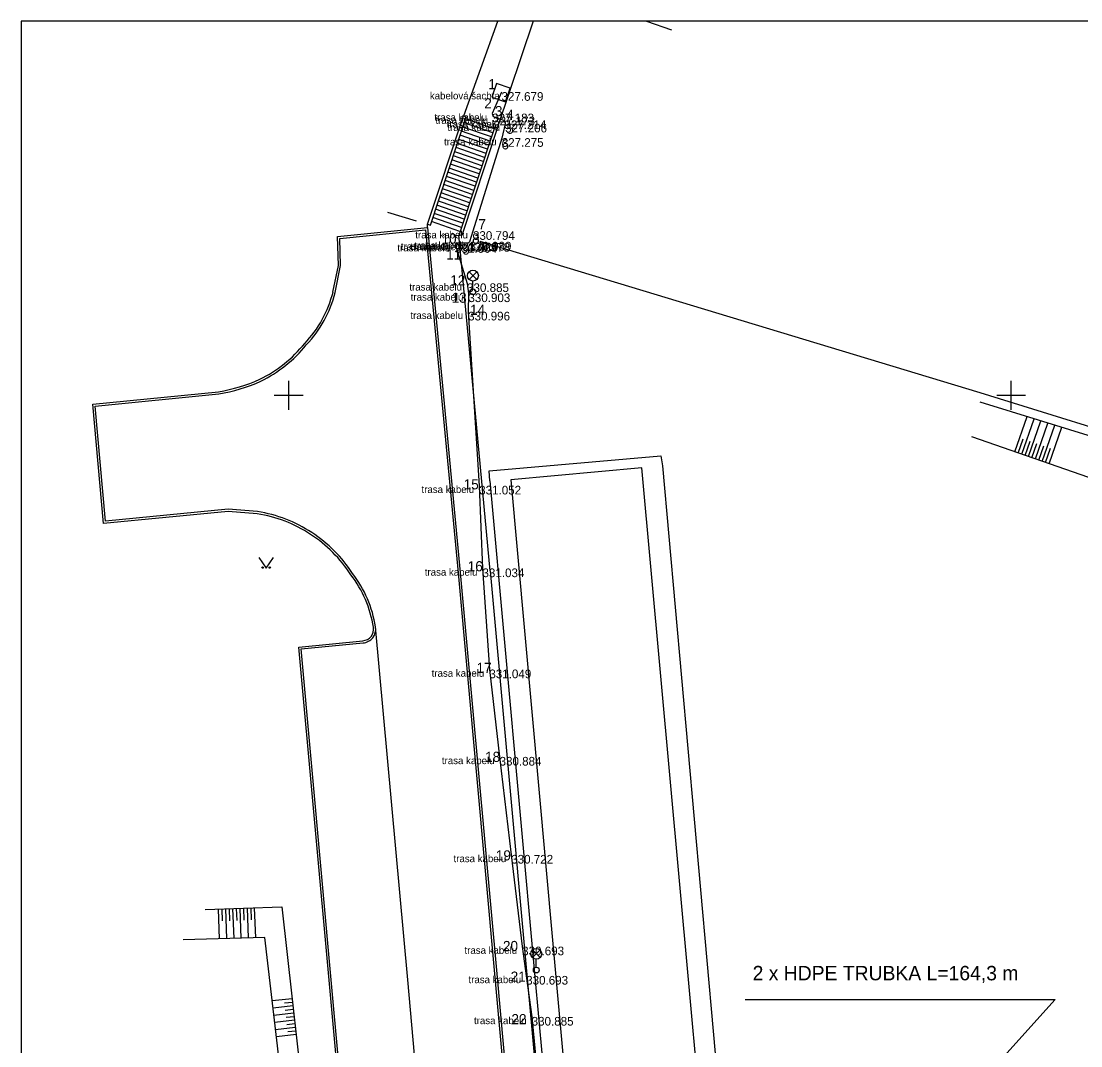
# Model space of a CAD drawing. Extents: x -825369 to -825236, y -1069674 to -1069474.
# Drawn here: x -825368.5 to -825295.2, y -1069545 to -1069474.1 of the extents above; entities that cross this region are included whole.
import ezdxf

# ---------------------------------------------------------------- set-up
doc = ezdxf.new("R2010")
doc.units = 0
for name, color, linetype in [('Vrstva 12', 7, 'Continuous'), ('Vrstva 18', 7, 'Continuous'), ('Vrstva 28', 7, 'Continuous'), ('Vrstva 29', 7, 'Continuous'), ('Vrstva 30', 7, 'Continuous'), ('Vrstva 31', 7, 'Continuous'), ('Vrstva 34', 7, 'Continuous'), ('Vrstva 37', 7, 'Continuous'), ('Vrstva 39', 7, 'Continuous'), ('Vrstva 4', 7, 'Continuous'), ('Vrstva 40', 7, 'Continuous'), ('Vrstva 41', 7, 'Continuous'), ('Vrstva 42', 7, 'Continuous'), ('Vrstva 49', 7, 'Continuous'), ('Vrstva 57', 7, 'Continuous'), ('Vrstva 58', 7, 'Continuous'), ('Vrstva 59', 7, 'Continuous'), ('Vrstva 60', 7, 'Continuous'), ('Vrstva 61', 7, 'Continuous'), ('Vrstva 63', 7, 'Continuous')]:
    doc.layers.add(name, color=color, linetype=linetype)

msp = doc.modelspace()

# ---------------------------------------------------------------- linework, layer by layer
at = {"layer": 'Vrstva 12'}
for p, q in [((-825337.513, -1069491.981), (-825336.985, -1069491.453)), ((-825336.977, -1069491.978), (-825337.505, -1069491.449)), ((-825337.249, -1069492.643), (-825337.249, -1069492.093)), ((-825333.129, -1069538.921), (-825332.601, -1069538.393)), ((-825332.593, -1069538.918), (-825333.121, -1069538.389)), ((-825332.865, -1069539.583), (-825332.865, -1069539.033))]:
    msp.add_line(p, q, dxfattribs=at)
for centre, radius in [((-825337.249, -1069491.718), 0.375), ((-825337.249, -1069492.843), 0.2), ((-825332.865, -1069538.658), 0.375), ((-825332.865, -1069539.783), 0.2)]:
    msp.add_circle(centre, radius, dxfattribs=at)
at = {"layer": 'Vrstva 18'}
msp.add_lwpolyline([(-825352.062, -1069511.227), (-825351.562, -1069511.977), (-825351.062, -1069511.227)], dxfattribs=at)
for centre in [(-825351.812, -1069511.927), (-825351.312, -1069511.927)]:
    msp.add_circle(centre, 0.05, dxfattribs=at)
at = {"layer": 'Vrstva 28'}
msp.add_lwpolyline([(-825325.239, -1069474.111), (-825323.513, -1069474.699)], dxfattribs=at)
at = {"layer": 'Vrstva 29'}
for points in [[(-825346.937, -1069492.861), (-825346.56, -1069491.012), (-825346.621, -1069489.019), (-825340.397, -1069488.395), (-825338.132, -1069512.267)], [(-825346.79, -1069492.891), (-825346.41, -1069491.025), (-825346.467, -1069489.154), (-825340.532, -1069488.559), (-825338.281, -1069512.281)], [(-825352.177, -1069508.206), (-825354.189, -1069508.041), (-825362.817, -1069508.879), (-825363.561, -1069500.626), (-825354.855, -1069499.762)], [(-825352.16, -1069508.057), (-825354.19, -1069507.89), (-825362.681, -1069508.715), (-825363.398, -1069500.761), (-825354.835, -1069499.911)], [(-825336.08, -1069505.921), (-825336.131, -1069505.225), (-825324.236, -1069504.188), (-825324.121, -1069504.884)], [(-825338.281, -1069512.281), (-825335.751, -1069540.051), (-825333.683, -1069562.857), (-825332.579, -1069575.035), (-825328.536, -1069619.676), (-825327.781, -1069628.092), (-825327.594, -1069630.111), (-825327.269, -1069633.089)], [(-825338.132, -1069512.267), (-825335.602, -1069540.037), (-825333.534, -1069562.843), (-825332.43, -1069575.021), (-825328.387, -1069619.663), (-825327.632, -1069628.078), (-825327.445, -1069630.096), (-825327.12, -1069633.076)], [(-825340.801, -1069562.686), (-825345.146, -1069563.101), (-825347.161, -1069540.989), (-825349.307, -1069517.426), (-825344.868, -1069516.99)], [(-825340.756, -1069562.531), (-825345.01, -1069562.937), (-825347.012, -1069540.975), (-825349.144, -1069517.561), (-825344.856, -1069517.139)]]:
    msp.add_lwpolyline(points, dxfattribs=at)
for centre, radius, start, end in [((-825354.646, -1069490.934), 7.946, 316.35812, 346.00973), ((-825354.646, -1069490.934), 8.096, 316.40023, 346.00973), ((-825356.123, -1069490.544), 9.313, 296.27067, 320.89871), ((-825356.123, -1069490.544), 9.463, 296.25278, 320.86273), ((-825356.899, -1069487.901), 12.036, 279.7781, 294.01605), ((-825356.899, -1069487.901), 12.186, 279.75272, 294.02992), ((-825353.552, -1069517.255), 9.153, 56.42368, 81.36038), ((-825353.552, -1069517.255), 9.303, 56.42838, 81.39226), ((-825353.641, -1069517.562), 9.458, 32.90184, 57.00596), ((-825353.641, -1069517.562), 9.608, 32.9379, 57.00142), ((-825352.062, -1069517.31), 8.021, 8.95558, 37.52175), ((-825352.062, -1069517.31), 8.171, 8.96274, 37.4793), ((-825344.922, -1069516.196), 0.795, 273.82755, 9.76725), ((-825344.922, -1069516.196), 0.945, 273.97601, 9.70035)]:
    msp.add_arc(centre, radius, start, end, dxfattribs=at)
at = {"layer": 'Vrstva 30'}
for p, q in [((-825337.877, -1069480.663), (-825335.522, -1069474.111)), ((-825333.093, -1069474.111), (-825335.553, -1069481.456)), ((-825340.397, -1069488.395), (-825340.389, -1069488.169)), ((-825336.067, -1069512.164), (-825338.222, -1069488.886))]:
    msp.add_line(p, q, dxfattribs=at)
msp.add_lwpolyline([(-825336.067, -1069512.164), (-825333.541, -1069539.857), (-825331.469, -1069562.554), (-825330.382, -1069574.7), (-825326.316, -1069619.52), (-825325.571, -1069627.823)], dxfattribs=at)
at = {"layer": 'Vrstva 31'}
for p, q in [((-825341.767, -1069540.45), (-825343.99, -1069516.037)), ((-825339.678, -1069563.407), (-825341.767, -1069540.45))]:
    msp.add_line(p, q, dxfattribs=at)
at = {"layer": 'Vrstva 34'}
msp.add_lwpolyline([(-825299.819, -1069635.63), (-825301.545, -1069616.501), (-825303.494, -1069616.672), (-825304.021, -1069611.198), (-825315.771, -1069612.283), (-825325.555, -1069505.027), (-825334.633, -1069505.856), (-825323.538, -1069628.443), (-825314.493, -1069627.62)], dxfattribs=at)
at = {"layer": 'Vrstva 37'}
for points in [[(-825324.121, -1069504.884), (-825320.184, -1069548.907), (-825314.729, -1069609.435)], [(-825336.08, -1069505.921), (-825332.957, -1069540.262), (-825330.948, -1069562.394), (-825329.816, -1069574.813), (-825325.748, -1069619.42), (-825324.98, -1069627.625)]]:
    msp.add_lwpolyline(points, dxfattribs=at)
at = {"layer": 'Vrstva 39'}
for p, q in [((-825341.164, -1069487.959), (-825343.151, -1069487.342)), ((-825302.149, -1069499.836), (-825336.746, -1069489.353)), ((-825263.556, -1069511.779), (-825302.149, -1069499.836)), ((-825302.149, -1069499.836), (-825302.149, -1069499.836))]:
    msp.add_line(p, q, dxfattribs=at)
at = {"layer": 'Vrstva 4'}
for p, q in [((-825340.389, -1069488.169), (-825337.901, -1069480.668)), ((-825340.199, -1069488.232), (-825337.711, -1069480.731)), ((-825337.901, -1069480.668), (-825337.711, -1069480.731)), ((-825335.871, -1069481.839), (-825337.85, -1069481.15)), ((-825335.777, -1069481.554), (-825337.756, -1069480.865)), ((-825335.731, -1069481.417), (-825338.214, -1069488.871)), ((-825336.156, -1069482.693), (-825338.134, -1069482.004)), ((-825336.061, -1069482.408), (-825338.039, -1069481.72)), ((-825335.541, -1069481.48), (-825338.024, -1069488.934)), ((-825335.966, -1069482.124), (-825337.945, -1069481.435)), ((-825335.731, -1069481.417), (-825335.541, -1069481.48)), ((-825336.44, -1069483.547), (-825338.417, -1069482.859)), ((-825336.346, -1069483.262), (-825338.322, -1069482.574)), ((-825336.251, -1069482.978), (-825338.228, -1069482.289)), ((-825336.63, -1069484.116), (-825338.606, -1069483.428)), ((-825336.535, -1069483.832), (-825338.511, -1069483.143)), ((-825336.914, -1069484.97), (-825338.889, -1069484.283)), ((-825336.82, -1069484.686), (-825338.795, -1069483.998)), ((-825336.725, -1069484.401), (-825338.7, -1069483.713)), ((-825337.104, -1069485.54), (-825339.078, -1069484.852)), ((-825337.009, -1069485.255), (-825338.984, -1069484.567)), ((-825337.389, -1069486.393), (-825339.361, -1069485.706)), ((-825337.294, -1069486.109), (-825339.267, -1069485.422)), ((-825337.199, -1069485.824), (-825339.173, -1069485.137)), ((-825337.578, -1069486.963), (-825339.55, -1069486.276)), ((-825337.483, -1069486.678), (-825339.456, -1069485.991)), ((-825337.863, -1069487.817), (-825339.834, -1069487.13)), ((-825337.768, -1069487.532), (-825339.739, -1069486.846)), ((-825337.673, -1069487.247), (-825339.645, -1069486.561)), ((-825338.147, -1069488.671), (-825340.117, -1069487.985)), ((-825338.052, -1069488.386), (-825340.023, -1069487.7)), ((-825337.957, -1069488.101), (-825339.928, -1069487.415)), ((-825340.389, -1069488.169), (-825340.199, -1069488.232)), ((-825338.214, -1069488.871), (-825338.024, -1069488.934))]:
    msp.add_line(p, q, dxfattribs=at)
at = {"layer": 'Vrstva 40'}
for points in [[(-825236.167, -1069524.332), (-825237.262, -1069523.999), (-825246.754, -1069520.202), (-825252.607, -1069519.062), (-825264.972, -1069515.496), (-825281.569, -1069509.919), (-825293.563, -1069506.065), (-825302.711, -1069502.888)], [(-825355.775, -1069535.603), (-825350.488, -1069535.412), (-825348.698, -1069551.291), (-825347.634, -1069563.35), (-825346.517, -1069570.517), (-825346.531, -1069576.662), (-825345.154, -1069589.955)]]:
    msp.add_lwpolyline(points, dxfattribs=at)
at = {"layer": 'Vrstva 41'}
for points in [[(-825251.05, -1069516.429), (-825263.841, -1069512.216), (-825276.773, -1069508.276), (-825287.871, -1069504.889), (-825302.141, -1069500.473)], [(-825346.308, -1069589.21), (-825348.589, -1069577.394), (-825347.861, -1069571.915), (-825349.159, -1069563.204), (-825350.03, -1069551.361), (-825351.662, -1069537.533), (-825357.31, -1069537.685)]]:
    msp.add_lwpolyline(points, dxfattribs=at)
at = {"layer": 'Vrstva 42'}
for p, q in [((-825299.741, -1069503.919), (-825298.894, -1069501.478)), ((-825299.269, -1069504.083), (-825298.416, -1069501.626)), ((-825298.797, -1069504.247), (-825297.938, -1069501.774)), ((-825298.324, -1069504.411), (-825297.46, -1069501.922)), ((-825297.852, -1069504.575), (-825296.982, -1069502.07)), ((-825297.38, -1069504.739), (-825296.504, -1069502.217)), ((-825299.505, -1069504.001), (-825299.166, -1069503.025)), ((-825299.033, -1069504.165), (-825298.691, -1069503.182)), ((-825298.561, -1069504.329), (-825298.217, -1069503.34)), ((-825298.088, -1069504.493), (-825297.742, -1069503.498)), ((-825297.616, -1069504.657), (-825297.268, -1069503.655)), ((-825354.88, -1069535.571), (-825354.806, -1069537.618)), ((-825354.63, -1069535.562), (-825354.6, -1069536.382)), ((-825354.38, -1069535.553), (-825354.306, -1069537.604)), ((-825354.13, -1069535.544), (-825354.101, -1069536.366)), ((-825353.881, -1069535.535), (-825353.806, -1069537.591)), ((-825353.631, -1069535.526), (-825353.601, -1069536.35)), ((-825353.381, -1069535.517), (-825353.306, -1069537.577)), ((-825353.131, -1069535.507), (-825353.101, -1069536.334)), ((-825352.881, -1069535.498), (-825352.807, -1069537.564)), ((-825352.631, -1069535.489), (-825352.602, -1069536.317)), ((-825352.382, -1069535.48), (-825352.307, -1069537.55)), ((-825349.771, -1069541.771), (-825351.144, -1069541.925)), ((-825349.743, -1069542.019), (-825350.292, -1069542.081)), ((-825349.715, -1069542.267), (-825351.085, -1069542.422)), ((-825349.659, -1069542.764), (-825351.026, -1069542.918)), ((-825349.687, -1069542.516), (-825350.235, -1069542.578)), ((-825349.603, -1069543.261), (-825350.968, -1069543.415)), ((-825349.631, -1069543.013), (-825350.178, -1069543.074)), ((-825349.575, -1069543.509), (-825350.121, -1069543.571)), ((-825349.547, -1069543.758), (-825350.909, -1069543.911)), ((-825349.491, -1069544.255), (-825350.851, -1069544.408)), ((-825349.519, -1069544.006), (-825350.064, -1069544.068))]:
    msp.add_line(p, q, dxfattribs=at)
at = {"layer": 'Vrstva 49'}
for p, q in [((-825335.627, -1069478.431), (-825335.946, -1069479.378)), ((-825334.68, -1069478.75), (-825335.627, -1069478.431)), ((-825334.999, -1069479.697), (-825334.68, -1069478.75)), ((-825335.946, -1069479.378), (-825334.999, -1069479.697)), ((-825329.363, -1069577.779), (-825296.951, -1069541.823)), ((-825318.409, -1069541.823), (-825296.951, -1069541.823))]:
    msp.add_line(p, q, dxfattribs=at)
msp.add_lwpolyline([(-825335.274, -1069479.021), (-825335.924, -1069480.509), (-825335.853, -1069480.717), (-825335.073, -1069480.98), (-825335.023, -1069481.208), (-825335.26, -1069482.206), (-825337.249, -1069488.646), (-825337.486, -1069489.381), (-825337.58, -1069489.463), (-825338.416, -1069489.444), (-825338.488, -1069489.542), (-825337.658, -1069492.255), (-825337.564, -1069492.952), (-825337.583, -1069494.222), (-825336.818, -1069506.267), (-825336.591, -1069511.99), (-825336.115, -1069518.985), (-825335.407, -1069525.032), (-825334.601, -1069531.815), (-825333.844, -1069538.163), (-825333.566, -1069540.191), (-825333.186, -1069543.028), (-825332.297, -1069552.187)], dxfattribs=at)
at = {"layer": 'Vrstva 57'}
for p, q in [((-825335.274, -1069479.021), (-825335.274, -1069479.021)), ((-825335.924, -1069480.509), (-825335.924, -1069480.509)), ((-825335.853, -1069480.717), (-825335.853, -1069480.717)), ((-825335.073, -1069480.98), (-825335.073, -1069480.98)), ((-825335.023, -1069481.208), (-825335.023, -1069481.208)), ((-825335.26, -1069482.206), (-825335.26, -1069482.206)), ((-825337.249, -1069488.646), (-825337.249, -1069488.646)), ((-825338.416, -1069489.444), (-825338.416, -1069489.444)), ((-825337.58, -1069489.463), (-825337.58, -1069489.463)), ((-825337.486, -1069489.381), (-825337.486, -1069489.381)), ((-825338.488, -1069489.542), (-825338.488, -1069489.542)), ((-825337.658, -1069492.255), (-825337.658, -1069492.255)), ((-825337.564, -1069492.952), (-825337.564, -1069492.952)), ((-825337.583, -1069494.222), (-825337.583, -1069494.222)), ((-825336.818, -1069506.267), (-825336.818, -1069506.267)), ((-825336.591, -1069511.99), (-825336.591, -1069511.99)), ((-825336.115, -1069518.985), (-825336.115, -1069518.985)), ((-825335.407, -1069525.032), (-825335.407, -1069525.032)), ((-825334.601, -1069531.815), (-825334.601, -1069531.815)), ((-825333.844, -1069538.163), (-825333.844, -1069538.163)), ((-825333.566, -1069540.191), (-825333.566, -1069540.191)), ((-825333.186, -1069543.028), (-825333.186, -1069543.028))]:
    msp.add_line(p, q, dxfattribs=at)
at = {"layer": 'Vrstva 58'}
for p, q in [((-825335.274, -1069479.021), (-825335.274, -1069479.021)), ((-825335.924, -1069480.509), (-825335.924, -1069480.509)), ((-825335.853, -1069480.717), (-825335.853, -1069480.717)), ((-825335.073, -1069480.98), (-825335.073, -1069480.98)), ((-825335.023, -1069481.208), (-825335.023, -1069481.208)), ((-825335.26, -1069482.206), (-825335.26, -1069482.206)), ((-825337.249, -1069488.646), (-825337.249, -1069488.646)), ((-825338.416, -1069489.444), (-825338.416, -1069489.444)), ((-825337.58, -1069489.463), (-825337.58, -1069489.463)), ((-825337.486, -1069489.381), (-825337.486, -1069489.381)), ((-825338.488, -1069489.542), (-825338.488, -1069489.542)), ((-825337.658, -1069492.255), (-825337.658, -1069492.255)), ((-825337.564, -1069492.952), (-825337.564, -1069492.952)), ((-825337.583, -1069494.222), (-825337.583, -1069494.222)), ((-825336.818, -1069506.267), (-825336.818, -1069506.267)), ((-825336.591, -1069511.99), (-825336.591, -1069511.99)), ((-825336.115, -1069518.985), (-825336.115, -1069518.985)), ((-825335.407, -1069525.032), (-825335.407, -1069525.032)), ((-825334.601, -1069531.815), (-825334.601, -1069531.815)), ((-825333.844, -1069538.163), (-825333.844, -1069538.163)), ((-825333.566, -1069540.191), (-825333.566, -1069540.191)), ((-825333.186, -1069543.028), (-825333.186, -1069543.028))]:
    msp.add_line(p, q, dxfattribs=at)
at = {"layer": 'Vrstva 63'}
for p, q in [((-825236.167, -1069474.111), (-825368.516, -1069474.111)), ((-825368.516, -1069474.111), (-825368.516, -1069673.689))]:
    msp.add_line(p, q, dxfattribs=at)
for points in [[(-825350, -1069501), (-825350, -1069500), (-825350, -1069499)], [(-825300, -1069501), (-825300, -1069500), (-825300, -1069499)], [(-825351, -1069500), (-825350, -1069500), (-825349, -1069500)], [(-825301, -1069500), (-825300, -1069500), (-825299, -1069500)]]:
    msp.add_lwpolyline(points, dxfattribs=at)

# ---------------------------------------------------------------- texts
at = {"layer": 'Vrstva 49'}
msp.add_text('2 x HDPE TRUBKA L=164,3 m', height=1, dxfattribs=at).set_placement((-825317.893, -1069540.495))
at = {"layer": 'Vrstva 59'}
for s, p in [('1', (-825336.186, -1069478.817)), ('2', (-825336.464, -1069480.146)), ('3', (-825335.729, -1069480.682)), ('4', (-825334.949, -1069480.945)), ('5', (-825334.943, -1069481.905)), ('6', (-825335.278, -1069482.986)), ('7', (-825336.877, -1069488.513)), ('10', (-825339.423, -1069489.51)), ('8', (-825337.314, -1069489.502)), ('11', (-825339.1, -1069490.611)), ('9', (-825337.975, -1069490.271)), ('12', (-825338.818, -1069492.392)), ('13', (-825338.724, -1069493.599)), ('14', (-825337.45, -1069494.435)), ('15', (-825337.89, -1069506.515)), ('16', (-825337.61, -1069512.185)), ('17', (-825337.001, -1069519.215)), ('18', (-825336.408, -1069525.378)), ('19', (-825335.664, -1069532.196)), ('20', (-825335.173, -1069538.47)), ('21', (-825334.638, -1069540.588)), ('22', (-825334.586, -1069543.533))]:
    msp.add_text(s, height=0.7, dxfattribs=at).set_placement(p)
at = {"layer": 'Vrstva 60'}
for s, p in [('327.679', (-825335.274, -1069479.621)), ('327.183', (-825335.924, -1069481.109)), ('327.173', (-825335.853, -1069481.317)), ('327.214', (-825335.073, -1069481.58)), ('327.206', (-825335.023, -1069481.808)), ('327.275', (-825335.26, -1069482.806)), ('330.794', (-825337.249, -1069489.246)), ('331.026', (-825338.416, -1069490.044)), ('330.978', (-825337.58, -1069490.063)), ('330.989', (-825337.486, -1069489.981)), ('331.004', (-825338.488, -1069490.142)), ('330.885', (-825337.658, -1069492.855)), ('330.903', (-825337.564, -1069493.552)), ('330.996', (-825337.583, -1069494.822)), ('331.052', (-825336.818, -1069506.867)), ('331.034', (-825336.591, -1069512.59)), ('331.049', (-825336.115, -1069519.585)), ('330.884', (-825335.407, -1069525.632)), ('330.722', (-825334.601, -1069532.415)), ('330.693', (-825333.844, -1069538.763)), ('330.693', (-825333.566, -1069540.791)), ('330.885', (-825333.186, -1069543.628))]:
    msp.add_text(s, height=0.6, dxfattribs=at).set_placement(p)
at = {"layer": 'Vrstva 61'}
for s, p in [('kabelová šachta', (-825340.23, -1069479.521)), ('trasa kabelu', (-825339.916, -1069481.009)), ('trasa kabelu', (-825339.845, -1069481.217)), ('trasa kabelu', (-825339.065, -1069481.48)), ('trasa kabelu', (-825339.015, -1069481.708)), ('trasa kabelu', (-825339.252, -1069482.706)), ('trasa kabelu', (-825341.241, -1069489.146)), ('trasa kabeli', (-825342.239, -1069489.944)), ('trasa kabelu', (-825341.572, -1069489.963)), ('trasa kabeli', (-825341.309, -1069489.881)), ('trasa kabelu', (-825342.48, -1069490.042)), ('trasa kabelu', (-825341.65, -1069492.755)), ('trasa kabelu', (-825341.556, -1069493.452)), ('trasa kabelu', (-825341.575, -1069494.722)), ('trasa kabelu', (-825340.81, -1069506.767)), ('trasa kabelu', (-825340.583, -1069512.49)), ('trasa kabelu', (-825340.107, -1069519.485)), ('trasa kabelu', (-825339.399, -1069525.532)), ('trasa kabelu', (-825338.593, -1069532.315)), ('trasa kabelu', (-825337.836, -1069538.663)), ('trasa kabelu', (-825337.558, -1069540.691)), ('trasa kabelu', (-825337.178, -1069543.528))]:
    msp.add_text(s, height=0.5, dxfattribs=at).set_placement(p)

doc.saveas('drawing.dxf')
